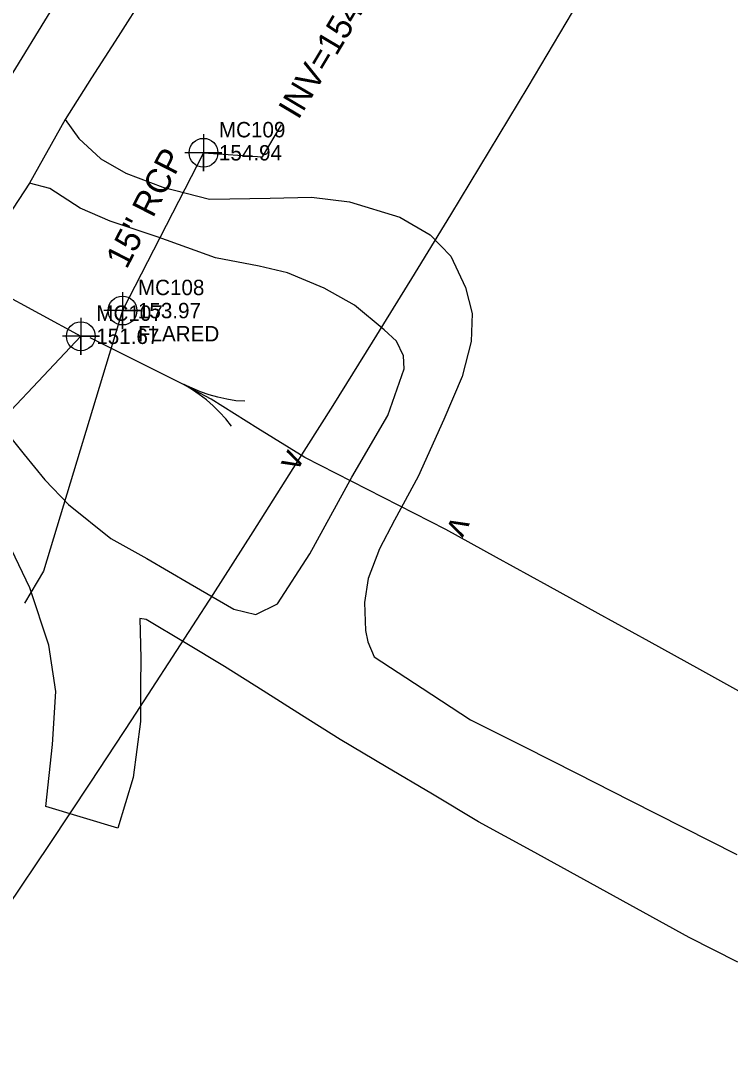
# Model space of a CAD drawing. Extents: x 2262665 to 2270527, y 505476 to 514960.
# Drawn here: x 2265890.1 to 2266005, y 508685.4 to 508854 of the extents above; entities that cross this region are included whole.
import ezdxf

# ---------------------------------------------------------------- set-up
doc = ezdxf.new("R2010")
doc.units = 0
for name, color, linetype in [('Exist Horizontal Alignment', 7, 'Continuous'), ('Exist Hydro Stream Flow Arrow CELL', 7, 'Continuous'), ('Exist Hydro Stream or Body of Water', 7, 'Continuous'), ('Exist Right of Way Control of Access Line', 7, 'Continuous'), ('Exist Roads EOP', 7, 'Continuous'), ('Exist Roads Soil', 7, 'Continuous'), ('Exist Structure Minor Culvert Topo', 7, 'Continuous'), ('Exist Structure Minor Culvert Topo Terminator', 7, 'Continuous'), ('Exist Structure Minor Pipes RCP 15 Inch', 7, 'Continuous'), ('Exist Structure Minor Pipes RCP 15 Inch Cogo Comment', 7, 'Continuous'), ('Exist Structure Minor Pipes RCP 15 Inch Cogo Elevation', 7, 'Continuous'), ('Exist Structure Minor Pipes RCP 15 Inch Cogo Number', 7, 'Continuous'), ('Exist Structure Minor Pipes RCP 15 Inch Cogo Point CELL', 7, 'Continuous'), ('Exist Structure Minor Pipes RCP 15 Inch Invert', 7, 'Continuous'), ('Exist Structure Minor Pipes RCP 15 Inch Leader', 7, 'Continuous'), ('Exist Structure Minor Pipes RCP 15 Inch Text', 7, 'Continuous')]:
    doc.layers.add(name, color=color, linetype=linetype)

msp = doc.modelspace()

# ---------------------------------------------------------------- linework, layer by layer
at = {"layer": 'Exist Horizontal Alignment'}
msp.add_arc((2263436.25, 510359.19), 2882, 309.60499, 355.6461, dxfattribs=at)
at = {"layer": 'Exist Hydro Stream Flow Arrow CELL'}
msp.add_line((2265920.89, 508792.65), (2265920.89, 508792.65), dxfattribs=at)
for points in [[(2265926.37, 508792.29), (2265924.91, 508792.39), (2265923.44, 508792.66), (2265921.99, 508792.95), (2265920.6, 508793.35), (2265919.2, 508793.83), (2265917.81, 508794.4), (2265916.49, 508795.03)], [(2265924.2, 508788.26), (2265923.31, 508789.43), (2265922.27, 508790.51), (2265921.24, 508791.57), (2265920.14, 508792.51), (2265918.97, 508793.42), (2265917.74, 508794.27), (2265916.49, 508795.03)]]:
    msp.add_lwpolyline(points, dxfattribs=at)
at = {"layer": 'Exist Hydro Stream or Body of Water'}
for points in [[(2265936.08, 508783.18), (2265928.48, 508787.91), (2265920.89, 508792.65), (2265916.22, 508795.12), (2265908.76, 508798.87), (2265901.3, 508802.61)], [(2266110.44, 508689.12), (2266102.8, 508693.24), (2266095.17, 508697.35), (2266087.53, 508701.46), (2266079.89, 508705.57), (2266072.25, 508709.69), (2266064.36, 508713.93), (2266056.46, 508718.17), (2266048.57, 508722.41), (2266040.67, 508726.66), (2266032.78, 508730.9), (2266024.88, 508735.14), (2266016.64, 508739.69), (2266008.4, 508744.23), (2266000.15, 508748.78), (2265991.91, 508753.32), (2265983.67, 508757.87), (2265975.42, 508762.41), (2265967.18, 508766.96), (2265958.94, 508771.5)]]:
    msp.add_lwpolyline(points, dxfattribs=at)
at = {"layer": 'Exist Right of Way Control of Access Line'}
for radius, end in [(2754.56, 355.6461), (2954.56, 339.73535)]:
    msp.add_arc((2263436.25, 510359.19), radius, 309.60499, end, dxfattribs=at)
at = {"layer": 'Exist Roads EOP'}
msp.add_lwpolyline([(2265910.12, 508858.21), (2265905.83, 508851.47), (2265901.54, 508844.73), (2265897.25, 508838), (2265891.48, 508827.67), (2265885.09, 508817.97)], dxfattribs=at)
at = {"layer": 'Exist Roads Soil'}
for points in [[(2265897.25, 508838), (2265899.47, 508834.93), (2265903.02, 508831.64), (2265907.09, 508829.27), (2265913.09, 508827.02), (2265920.67, 508825.1), (2265930.48, 508825.26), (2265937.16, 508825.42), (2265943.32, 508824.63), (2265951.52, 508822.18), (2265956.4, 508819.31), (2265959.74, 508815.82), (2265962.12, 508810.74), (2265963.24, 508806.55), (2265963.07, 508801.97), (2265961.58, 508796.3), (2265958.63, 508789.36), (2265954.45, 508780.11), (2265950.62, 508773), (2265948.18, 508768.38), (2265946.34, 508763.58), (2265945.79, 508759.65), (2265945.93, 508755.11), (2265946.33, 508753.26), (2265947.31, 508750.86), (2265955.14, 508745.76), (2265962.97, 508740.66), (2265971.6, 508736.29), (2265980.23, 508731.92), (2265988.85, 508727.55), (2265997.48, 508723.18), (2266006.11, 508718.81)], [(2265887.56, 508787.45), (2265890.6, 508783.65), (2265893.95, 508779.55), (2265897.8, 508775.55), (2265904.64, 508770.02), (2265910.46, 508766.82), (2265917.52, 508762.69), (2265924.57, 508758.56), (2265928.17, 508757.71), (2265931.67, 508759.43), (2265936.9, 508767.55), (2265940.31, 508773.78), (2265943.73, 508780.01), (2265949.54, 508789.99), (2265952.18, 508797.56), (2265952.11, 508799.68), (2265950.94, 508802.03), (2265948.96, 508803.87), (2265944.17, 508807.86), (2265939.24, 508810.66), (2265933.27, 508813.13), (2265928.68, 508814.23), (2265921.64, 508815.54), (2265912.3, 508818.9), (2265904.57, 508821.53), (2265899.68, 508823.61), (2265894.76, 508826.82), (2265891.48, 508827.67)], [(2266006.26, 508701.32), (2265998.38, 508705.36), (2265989.84, 508710.04), (2265981.3, 508714.73), (2265972.77, 508719.42), (2265964.23, 508724.11), (2265956.77, 508728.56), (2265949.3, 508733.01), (2265941.84, 508737.46), (2265935.58, 508741.4), (2265929.33, 508745.34), (2265923.08, 508749.28), (2265916.72, 508753.1), (2265910.37, 508756.93), (2265909.33, 508757.08), (2265909.53, 508750.66), (2265909.48, 508746.15), (2265909.45, 508740.39), (2265908.29, 508731.29), (2265905.77, 508723.07), (2265894.14, 508726.57), (2265895.18, 508736.62), (2265895.75, 508745.21), (2265894.58, 508752.72), (2265891.5, 508762.02), (2265887.34, 508770.72)]]:
    msp.add_lwpolyline(points, dxfattribs=at)
at = {"layer": 'Exist Structure Minor Culvert Topo'}
msp.add_line((2265958.94, 508771.5), (2265936.08, 508783.18), dxfattribs=at)
at = {"layer": 'Exist Structure Minor Pipes RCP 15 Inch'}
for p, q in [((2265919.67, 508832.6), (2265906.54, 508807.01)), ((2265848.19, 508830.94), (2265899.79, 508802.84))]:
    msp.add_line(p, q, dxfattribs=at)
at = {"layer": 'Exist Structure Minor Pipes RCP 15 Inch Cogo Point CELL'}
for points in [[(2265919.67, 508835.6), (2265919.67, 508829.6), (2265919.67, 508832.6), (2265922.67, 508832.6), (2265916.67, 508832.6)], [(2265906.54, 508810.01), (2265906.54, 508804.01), (2265906.54, 508807.01), (2265909.54, 508807.01), (2265903.54, 508807.01)], [(2265899.79, 508805.84), (2265899.79, 508799.84), (2265899.79, 508802.84), (2265902.79, 508802.84), (2265896.79, 508802.84)]]:
    msp.add_lwpolyline(points, dxfattribs=at)
for centre in [(2265919.67, 508832.6), (2265906.54, 508807.01), (2265899.79, 508802.84)]:
    msp.add_circle(centre, 2.34, dxfattribs=at)
at = {"layer": 'Exist Structure Minor Pipes RCP 15 Inch Leader'}
for points in [[(2265919.67, 508832.6), (2265929.23, 508831.97), (2265932.3, 508837.12)], [(2265906.54, 508807.01), (2265893.72, 508764.72), (2265890.65, 508759.56)], [(2265899.79, 508802.84), (2265881.54, 508783.48), (2265878.48, 508778.32)]]:
    msp.add_lwpolyline(points, dxfattribs=at)

# ---------------------------------------------------------------- texts
at = {"layer": 'Exist Structure Minor Culvert Topo Terminator'}
for rotation, p in [(63.4308, (2265934.89, 508780.81)), (243.4308, (2265960.12, 508773.87))]:
    msp.add_text('v', height=4, rotation=rotation, dxfattribs=at).set_placement(p)
at = {"layer": 'Exist Structure Minor Pipes RCP 15 Inch Cogo Comment'}
msp.add_text('FLARED', height=2.5, dxfattribs=at).set_placement((2265909.04, 508802.01))
at = {"layer": 'Exist Structure Minor Pipes RCP 15 Inch Cogo Elevation'}
for s, p in [('154.94', (2265922.17, 508831.35)), ('153.97', (2265909.04, 508805.76)), ('151.67', (2265902.29, 508801.59))]:
    msp.add_text(s, height=2.5, dxfattribs=at).set_placement(p)
at = {"layer": 'Exist Structure Minor Pipes RCP 15 Inch Cogo Number'}
for s, p in [('MC109', (2265922.17, 508835.1)), ('MC108', (2265909.04, 508809.51)), ('MC107', (2265902.29, 508805.34))]:
    msp.add_text(s, height=2.5, dxfattribs=at).set_placement(p)
at = {"layer": 'Exist Structure Minor Pipes RCP 15 Inch Invert'}
msp.add_text("INV=154.94'", height=4, rotation=59.2519, dxfattribs=at).set_placement((2265935.04, 508837.82))
at = {"layer": 'Exist Structure Minor Pipes RCP 15 Inch Text'}
msp.add_text('15" RCP', height=4, rotation=62.8415, dxfattribs=at).set_placement((2265907.22, 508813.6))

doc.saveas('drawing.dxf')
